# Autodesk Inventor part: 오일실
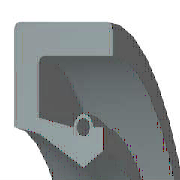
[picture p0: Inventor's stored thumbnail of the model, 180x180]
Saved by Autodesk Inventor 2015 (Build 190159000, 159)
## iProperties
IsCustomPart: 1
Created: 2015-10
Part Number: 오일실
Material: 고무
Description: 오일-실
Document SubType Name: Modeling
Standard: KS B 2804
Designer: mdu
Standards Organization: KS
Language: ko-KR
Size Designation: S - 25 38 8
Categories: <MemberInstance><Categories><Category DisplayName="샤프트 부품" InternalName="7f7aeb1f-a693-4053-b835-cee3144e0d98" Mnemonic="SHFT"><Category DisplayName="실링" Intern
Density: 0.93 g/cm^3
Appearance: 고무 - 검은색 - 버전 1.1
Author: mdu
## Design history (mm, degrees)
revolve "본체" stored, may be unused: angle "d17" = 90 deg
revolve "스프링1" stored, may be unused: angle "d18" = 90 deg
body "Solid1"
sketch "스케치1"
  geometry: L1 (0, 19)-(8, 19); L2 (8, 19)-(8, 17.75); L3 (8, 17.75)-(1.75, 17.75); L4 (0, 19)-(0, 14.6); L5 (0, 14.6)-(1.75, 14.25); L6 (1.75, 14.25)-(4.9, 12.5); L7 (4.9, 12.5)-(0, 12.5); L8 (6.3, 13.375)-(6.3, 14.6); L9 (0, 0)-(9.586, 0) reference; L10 (4.9, 12.5)-(6.3, 13.375); L11 (0, 18)-(0, -3) reference; L12 (-1.917, 0)-(11.503, 0) reference; L13 (4.2, 14.6)-(1.75, 15.09); L14 (1.75, 15.09)-(1.75, 17.75); L15 (6.3, 14.6)-(5.6, 14.6); C1 r 0.455 at (4.9, 14.6); A1 r 0.7 centre (4.9, 14.6) between (5.6, 14.6) and (4.2, 14.6)
  constraints: 26 end point, 5 horizontal alignment, 4 perpendicular, 2 centre point, 2 collinear, 2 horizontal, 2 parallel, 2 point on circle, 2 point on line, 2 vertical alignment, 1 coincident
  dimensions: "d0" = 38 diameter of L1 L9 (= SD2); "d1" = 26.75 diameter of L8.start L9 (= ABDM); "d2" = 1.25 distance of L1.end L2.end (computed from SD); "d3" = 0.91 diameter of C1 (= SPDI); "d4" = 1.4 diameter of A1 (= SPDA); "d5" = 25 diameter of L6.end L9 (= NND); "d6" = 28.5 diameter of L5.end L9 (= TKDM); "d7" = 29.2 diameter of L4.end L9 (= HLDM); "d8" = 4.9 distance from line of C1.centre L4 (= SPDST); "d9" = 6.3 distance between parallel lines of L8 L4 (= SDI); "d10" = 8 distance between parallel lines of L2 L4 (= SWDT); "d12" = 1.75 distance between parallel lines of L14 L4 (= SD)
fillet "모깎기1" dims "d11" = 0.3 (= RR)
other parameters: "SD2" = 38 [user parameter; used in 1 equation term], "SWDT" = 8 [user parameter; used in 1 equation term], "RR" = 0.3 [user parameter; used in 1 equation term], "SD" = 1.75 [user parameter; used in 2 equation terms], "NND" = 25 [user parameter; used in 1 equation term], "SPDA" = 1.4 [user parameter; used in 1 equation term], "SPDI" = 0.91 [user parameter; used in 1 equation term], "TKDM" = 28.5 [user parameter; used in 1 equation term], "HLDM" = 29.2 [user parameter; used in 1 equation term], "ABDM" = 26.75 [user parameter; used in 1 equation term], "SDI" = 6.3 [user parameter; used in 1 equation term], "SPDST" = 4.9 [user parameter; used in 1 equation term], "d13" = 0, "d14" = 0, "d15" = 0, "LAB" = 0.35 [user parameter]
